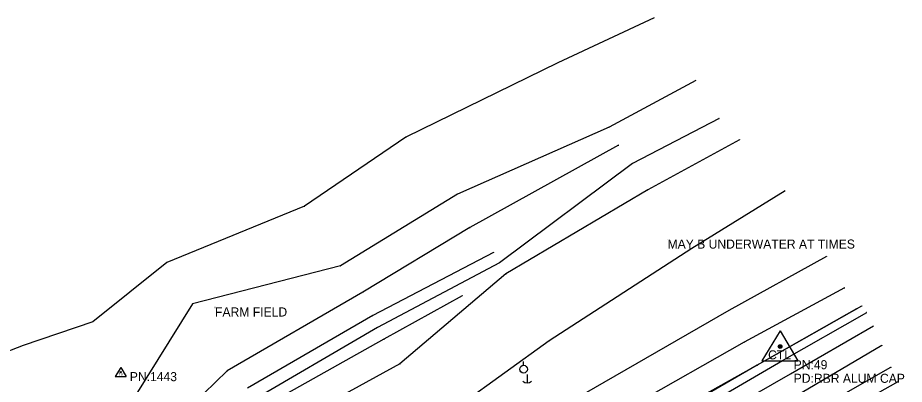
# Model space of a CAD drawing. Extents: x 1419505 to 1434054, y 1956910 to 1968644.
# Drawn here: x 1423305.2 to 1423793.8, y 1959349.3 to 1959551.5 of the extents above; entities that cross this region are included whole.
import ezdxf

# ---------------------------------------------------------------- set-up
doc = ezdxf.new("R2010")
doc.units = 0
for name, color, linetype in [('S_BREAKLINE', 7, 'Continuous'), ('S_DITCHLINE', 7, 'Continuous'), ('S_EDGE_PAVEMENT', 7, 'Continuous'), ('S_GRD_PT_SYM', 7, 'Continuous'), ('S_MSC_PT_SYM', 7, 'Continuous'), ('S_PAVEMENT_CROWN', 7, 'Continuous'), ('S_PRIMARY_CTL', 7, 'Continuous'), ('S_PRIMARY_CTL_ANNOT', 7, 'Continuous'), ('S_RDW_PT_SYM', 7, 'Continuous'), ('S_SECONDARY_CTL', 7, 'Continuous'), ('S_SECONDARY_CTL_ANNOT', 7, 'Continuous'), ('S_SHOULDER', 7, 'Continuous'), ('S_SURVEY_TEXT_ANNOT', 7, 'Continuous'), ('S_UTILITY_POLE', 7, 'Continuous')]:
    doc.layers.add(name, color=color, linetype=linetype)

msp = doc.modelspace()

# ---------------------------------------------------------------- linework, layer by layer
at = {"layer": 'S_BREAKLINE'}
for p, q in [((1423655.9493, 1959551.4129), (1423602.8278, 1959526.6033)), ((1423602.8278, 1959526.6033), (1423519.0004, 1959485.5276)), ((1423678.9158, 1959516.8316), (1423631.0697, 1959491.18)), ((1423631.0697, 1959491.18), (1423547.5183, 1959454.1426)), ((1423519.0004, 1959485.5276), (1423463.2938, 1959447.6392)), ((1423702.9793, 1959484.1715), (1423652.393, 1959456.5407)), ((1423636.372, 1959481.2103), (1423554.3977, 1959435.7824)), ((1423547.5183, 1959454.1426), (1423483.1441, 1959414.669)), ((1423652.393, 1959456.5407), (1423574.271, 1959410.1767)), ((1423728.1139, 1959455.9897), (1423676.7066, 1959424.1897)), ((1423463.2938, 1959447.6392), (1423387.3729, 1959416.4552)), ((1423554.3977, 1959435.7824), (1423495.3649, 1959400.0781)), ((1423676.7066, 1959424.1897), (1423598.1405, 1959373.3034)), ((1423750.9134, 1959419.7534), (1423697.1119, 1959390.0745)), ((1423387.3729, 1959416.4552), (1423346.5723, 1959383.846)), ((1423483.1441, 1959414.669), (1423401.5338, 1959393.6317)), ((1423574.271, 1959410.1767), (1423515.8552, 1959360.5385)), ((1423495.3649, 1959400.0781), (1423420.6961, 1959356.6703)), ((1423760.9351, 1959402.4883), (1423705.6115, 1959372.5493)), ((1423550.0934, 1959398.197), (1423507.0107, 1959374.1404)), ((1423401.5338, 1959393.6317), (1423369.4308, 1959342.0964)), ((1423697.1119, 1959390.0745), (1423617.2978, 1959344.1385)), ((1423767.5305, 1959391.0025), (1423712.7709, 1959359.8295)), ((1423723.3576, 1959365.9369), (1423770.4067, 1959392.5266)), ((1423346.5723, 1959383.846), (1423308.1598, 1959370.7032)), ((1423308.1598, 1959370.7032), (1423285.4454, 1959361.8876)), ((1423507.0107, 1959374.1404), (1423432.3018, 1959332.4447)), ((1423598.1405, 1959373.3034), (1423534.3444, 1959327.3684)), ((1423705.6115, 1959372.5493), (1423625.4253, 1959327.0984)), ((1423677.4347, 1959340.1152), (1423723.3576, 1959365.9369)), ((1423420.6961, 1959356.6703), (1423381.7956, 1959319.3479)), ((1423515.8552, 1959360.5385), (1423445.3007, 1959322.0911)), ((1423712.7709, 1959359.8295), (1423633.4068, 1959314.0375))]:
    msp.add_line(p, q, dxfattribs=at)
at = {"layer": 'S_DITCHLINE'}
for p, q in [((1423691.6846, 1959495.8783), (1423643.9965, 1959471.1427)), ((1423643.9965, 1959471.1427), (1423570.7108, 1959416.3331)), ((1423567.3906, 1959422.0785), (1423500.8393, 1959387.3443)), ((1423570.7108, 1959416.3331), (1423503.4494, 1959380.6948)), ((1423500.8393, 1959387.3443), (1423431.7848, 1959347.1597)), ((1423503.4494, 1959380.6948), (1423430.4317, 1959337.9941))]:
    msp.add_line(p, q, dxfattribs=at)
at = {"layer": 'S_EDGE_PAVEMENT'}
for p, q in [((1423731.1311, 1959355.0572), (1423776.8571, 1959381.5699)), ((1423743.1339, 1959334.1888), (1423786.4687, 1959358.7254)), ((1423684.7071, 1959328.5905), (1423731.1311, 1959355.0572))]:
    msp.add_line(p, q, dxfattribs=at)
at = {"layer": 'S_GRD_PT_SYM'}
for points in [[(1423655.9493, 1959551.4129), (1423655.9493, 1959551.4629), (1423655.9493, 1959551.4129), (1423655.8993, 1959551.4129), (1423655.9493, 1959551.4129), (1423655.9493, 1959551.3629), (1423655.9493, 1959551.4129), (1423655.9993, 1959551.4129)], [(1423602.8278, 1959526.6033), (1423602.8278, 1959526.6533), (1423602.8278, 1959526.6033), (1423602.7778, 1959526.6033), (1423602.8278, 1959526.6033), (1423602.8278, 1959526.5533), (1423602.8278, 1959526.6033), (1423602.8778, 1959526.6033)], [(1423678.9158, 1959516.8316), (1423678.9158, 1959516.8816), (1423678.9158, 1959516.8316), (1423678.8658, 1959516.8316), (1423678.9158, 1959516.8316), (1423678.9158, 1959516.7816), (1423678.9158, 1959516.8316), (1423678.9658, 1959516.8316)], [(1423691.6846, 1959495.8783), (1423691.6846, 1959495.9283), (1423691.6846, 1959495.8783), (1423691.6346, 1959495.8783), (1423691.6846, 1959495.8783), (1423691.6846, 1959495.8283), (1423691.6846, 1959495.8783), (1423691.7346, 1959495.8783)], [(1423631.0697, 1959491.18), (1423631.0697, 1959491.23), (1423631.0697, 1959491.18), (1423631.0197, 1959491.18), (1423631.0697, 1959491.18), (1423631.0697, 1959491.13), (1423631.0697, 1959491.18), (1423631.1197, 1959491.18)], [(1423519.0004, 1959485.5276), (1423519.0004, 1959485.5776), (1423519.0004, 1959485.5276), (1423518.9504, 1959485.5276), (1423519.0004, 1959485.5276), (1423519.0004, 1959485.4776), (1423519.0004, 1959485.5276), (1423519.0504, 1959485.5276)], [(1423702.9793, 1959484.1715), (1423702.9793, 1959484.2215), (1423702.9793, 1959484.1715), (1423702.9293, 1959484.1715), (1423702.9793, 1959484.1715), (1423702.9793, 1959484.1215), (1423702.9793, 1959484.1715), (1423703.0293, 1959484.1715)], [(1423636.372, 1959481.2103), (1423636.372, 1959481.2603), (1423636.372, 1959481.2103), (1423636.322, 1959481.2103), (1423636.372, 1959481.2103), (1423636.372, 1959481.1603), (1423636.372, 1959481.2103), (1423636.422, 1959481.2103)], [(1423643.9965, 1959471.1427), (1423643.9965, 1959471.1927), (1423643.9965, 1959471.1427), (1423643.9465, 1959471.1427), (1423643.9965, 1959471.1427), (1423643.9965, 1959471.0927), (1423643.9965, 1959471.1427), (1423644.0465, 1959471.1427)], [(1423547.5183, 1959454.1426), (1423547.5183, 1959454.1926), (1423547.5183, 1959454.1426), (1423547.4683, 1959454.1426), (1423547.5183, 1959454.1426), (1423547.5183, 1959454.0926), (1423547.5183, 1959454.1426), (1423547.5683, 1959454.1426)], [(1423652.393, 1959456.5407), (1423652.393, 1959456.5907), (1423652.393, 1959456.5407), (1423652.343, 1959456.5407), (1423652.393, 1959456.5407), (1423652.393, 1959456.4907), (1423652.393, 1959456.5407), (1423652.443, 1959456.5407)], [(1423728.1139, 1959455.9897), (1423728.1139, 1959456.0397), (1423728.1139, 1959455.9897), (1423728.0639, 1959455.9897), (1423728.1139, 1959455.9897), (1423728.1139, 1959455.9397), (1423728.1139, 1959455.9897), (1423728.1639, 1959455.9897)], [(1423463.2938, 1959447.6392), (1423463.2938, 1959447.6892), (1423463.2938, 1959447.6392), (1423463.2438, 1959447.6392), (1423463.2938, 1959447.6392), (1423463.2938, 1959447.5892), (1423463.2938, 1959447.6392), (1423463.3438, 1959447.6392)], [(1423554.3977, 1959435.7824), (1423554.3977, 1959435.8324), (1423554.3977, 1959435.7824), (1423554.3477, 1959435.7824), (1423554.3977, 1959435.7824), (1423554.3977, 1959435.7324), (1423554.3977, 1959435.7824), (1423554.4477, 1959435.7824)], [(1423676.7066, 1959424.1897), (1423676.7066, 1959424.2397), (1423676.7066, 1959424.1897), (1423676.6566, 1959424.1897), (1423676.7066, 1959424.1897), (1423676.7066, 1959424.1397), (1423676.7066, 1959424.1897), (1423676.7566, 1959424.1897)], [(1423567.3906, 1959422.0785), (1423567.3906, 1959422.1285), (1423567.3906, 1959422.0785), (1423567.3406, 1959422.0785), (1423567.3906, 1959422.0785), (1423567.3906, 1959422.0285), (1423567.3906, 1959422.0785), (1423567.4406, 1959422.0785)], [(1423750.9134, 1959419.7534), (1423750.9134, 1959419.8034), (1423750.9134, 1959419.7534), (1423750.8634, 1959419.7534), (1423750.9134, 1959419.7534), (1423750.9134, 1959419.7034), (1423750.9134, 1959419.7534), (1423750.9634, 1959419.7534)], [(1423387.3729, 1959416.4552), (1423387.3729, 1959416.5052), (1423387.3729, 1959416.4552), (1423387.3229, 1959416.4552), (1423387.3729, 1959416.4552), (1423387.3729, 1959416.4052), (1423387.3729, 1959416.4552), (1423387.4229, 1959416.4552)], [(1423483.1441, 1959414.669), (1423483.1441, 1959414.719), (1423483.1441, 1959414.669), (1423483.0941, 1959414.669), (1423483.1441, 1959414.669), (1423483.1441, 1959414.619), (1423483.1441, 1959414.669), (1423483.1941, 1959414.669)], [(1423570.7108, 1959416.3331), (1423570.7108, 1959416.3831), (1423570.7108, 1959416.3331), (1423570.6608, 1959416.3331), (1423570.7108, 1959416.3331), (1423570.7108, 1959416.2831), (1423570.7108, 1959416.3331), (1423570.7608, 1959416.3331)], [(1423574.271, 1959410.1767), (1423574.271, 1959410.2267), (1423574.271, 1959410.1767), (1423574.221, 1959410.1767), (1423574.271, 1959410.1767), (1423574.271, 1959410.1267), (1423574.271, 1959410.1767), (1423574.321, 1959410.1767)], [(1423495.3649, 1959400.0781), (1423495.3649, 1959400.1281), (1423495.3649, 1959400.0781), (1423495.3149, 1959400.0781), (1423495.3649, 1959400.0781), (1423495.3649, 1959400.0281), (1423495.3649, 1959400.0781), (1423495.4149, 1959400.0781)], [(1423760.9351, 1959402.4883), (1423760.9351, 1959402.5383), (1423760.9351, 1959402.4883), (1423760.8851, 1959402.4883), (1423760.9351, 1959402.4883), (1423760.9351, 1959402.4383), (1423760.9351, 1959402.4883), (1423760.9851, 1959402.4883)], [(1423550.0934, 1959398.197), (1423550.0934, 1959398.247), (1423550.0934, 1959398.197), (1423550.0434, 1959398.197), (1423550.0934, 1959398.197), (1423550.0934, 1959398.147), (1423550.0934, 1959398.197), (1423550.1434, 1959398.197)], [(1423401.5338, 1959393.6317), (1423401.5338, 1959393.6817), (1423401.5338, 1959393.6317), (1423401.4838, 1959393.6317), (1423401.5338, 1959393.6317), (1423401.5338, 1959393.5817), (1423401.5338, 1959393.6317), (1423401.5838, 1959393.6317)], [(1423697.1119, 1959390.0745), (1423697.1119, 1959390.1245), (1423697.1119, 1959390.0745), (1423697.0619, 1959390.0745), (1423697.1119, 1959390.0745), (1423697.1119, 1959390.0245), (1423697.1119, 1959390.0745), (1423697.1619, 1959390.0745)], [(1423767.5305, 1959391.0025), (1423767.5305, 1959391.0525), (1423767.5305, 1959391.0025), (1423767.4805, 1959391.0025), (1423767.5305, 1959391.0025), (1423767.5305, 1959390.9525), (1423767.5305, 1959391.0025), (1423767.5805, 1959391.0025)], [(1423770.4067, 1959392.5266), (1423770.4067, 1959392.5766), (1423770.4067, 1959392.5266), (1423770.3567, 1959392.5266), (1423770.4067, 1959392.5266), (1423770.4067, 1959392.4766), (1423770.4067, 1959392.5266), (1423770.4567, 1959392.5266)], [(1423500.8393, 1959387.3443), (1423500.8393, 1959387.3943), (1423500.8393, 1959387.3443), (1423500.7893, 1959387.3443), (1423500.8393, 1959387.3443), (1423500.8393, 1959387.2943), (1423500.8393, 1959387.3443), (1423500.8893, 1959387.3443)], [(1423346.5723, 1959383.846), (1423346.5723, 1959383.896), (1423346.5723, 1959383.846), (1423346.5223, 1959383.846), (1423346.5723, 1959383.846), (1423346.5723, 1959383.796), (1423346.5723, 1959383.846), (1423346.6223, 1959383.846)], [(1423503.4494, 1959380.6948), (1423503.4494, 1959380.7448), (1423503.4494, 1959380.6948), (1423503.3994, 1959380.6948), (1423503.4494, 1959380.6948), (1423503.4494, 1959380.6448), (1423503.4494, 1959380.6948), (1423503.4994, 1959380.6948)], [(1423308.1598, 1959370.7032), (1423308.1598, 1959370.7532), (1423308.1598, 1959370.7032), (1423308.1098, 1959370.7032), (1423308.1598, 1959370.7032), (1423308.1598, 1959370.6532), (1423308.1598, 1959370.7032), (1423308.2098, 1959370.7032)], [(1423507.0107, 1959374.1404), (1423507.0107, 1959374.1904), (1423507.0107, 1959374.1404), (1423506.9607, 1959374.1404), (1423507.0107, 1959374.1404), (1423507.0107, 1959374.0904), (1423507.0107, 1959374.1404), (1423507.0607, 1959374.1404)], [(1423598.1405, 1959373.3034), (1423598.1405, 1959373.3534), (1423598.1405, 1959373.3034), (1423598.0905, 1959373.3034), (1423598.1405, 1959373.3034), (1423598.1405, 1959373.2534), (1423598.1405, 1959373.3034), (1423598.1905, 1959373.3034)], [(1423705.6115, 1959372.5493), (1423705.6115, 1959372.5993), (1423705.6115, 1959372.5493), (1423705.5615, 1959372.5493), (1423705.6115, 1959372.5493), (1423705.6115, 1959372.4993), (1423705.6115, 1959372.5493), (1423705.6615, 1959372.5493)], [(1423723.3576, 1959365.9369), (1423723.3576, 1959365.9869), (1423723.3576, 1959365.9369), (1423723.3076, 1959365.9369), (1423723.3576, 1959365.9369), (1423723.3576, 1959365.8869), (1423723.3576, 1959365.9369), (1423723.4076, 1959365.9369)], [(1423420.6961, 1959356.6703), (1423420.6961, 1959356.7203), (1423420.6961, 1959356.6703), (1423420.6461, 1959356.6703), (1423420.6961, 1959356.6703), (1423420.6961, 1959356.6203), (1423420.6961, 1959356.6703), (1423420.7461, 1959356.6703)], [(1423515.8552, 1959360.5385), (1423515.8552, 1959360.5885), (1423515.8552, 1959360.5385), (1423515.8052, 1959360.5385), (1423515.8552, 1959360.5385), (1423515.8552, 1959360.4885), (1423515.8552, 1959360.5385), (1423515.9052, 1959360.5385)], [(1423712.7709, 1959359.8295), (1423712.7709, 1959359.8795), (1423712.7709, 1959359.8295), (1423712.7209, 1959359.8295), (1423712.7709, 1959359.8295), (1423712.7709, 1959359.7795), (1423712.7709, 1959359.8295), (1423712.8209, 1959359.8295)]]:
    msp.add_lwpolyline(points, dxfattribs=at)
at = {"layer": 'S_MSC_PT_SYM'}
for points in [[(1423663.3078, 1959429.157), (1423663.3078, 1959429.207), (1423663.3078, 1959429.157), (1423663.2578, 1959429.157), (1423663.3078, 1959429.157), (1423663.3078, 1959429.107), (1423663.3078, 1959429.157), (1423663.3578, 1959429.157)], [(1423413.9216, 1959391.7046), (1423413.9216, 1959391.7546), (1423413.9216, 1959391.7046), (1423413.8716, 1959391.7046), (1423413.9216, 1959391.7046), (1423413.9216, 1959391.6546), (1423413.9216, 1959391.7046), (1423413.9716, 1959391.7046)]]:
    msp.add_lwpolyline(points, dxfattribs=at)
at = {"layer": 'S_PAVEMENT_CROWN'}
msp.add_line((1423737.4865, 1959345.0415), (1423781.4454, 1959370.8402), dxfattribs=at)
at = {"layer": 'S_PRIMARY_CTL'}
for p, q in [((1423725.3418, 1959378.8356), (1423715.3085, 1959362.3224)), ((1423725.3418, 1959378.8356), (1423735.1661, 1959362.3224)), ((1423715.3085, 1959362.3224), (1423735.1661, 1959362.3224))]:
    msp.add_line(p, q, dxfattribs=at)
for radius in [1.0369, 0.6089, 0.3444]:
    msp.add_circle((1423725.3418, 1959370.1352), radius, dxfattribs=at)
at = {"layer": 'S_RDW_PT_SYM'}
for points in [[(1423773.1068, 1959388.9114), (1423773.1068, 1959388.9614), (1423773.1068, 1959388.9114), (1423773.0568, 1959388.9114), (1423773.1068, 1959388.9114), (1423773.1068, 1959388.8614), (1423773.1068, 1959388.9114), (1423773.1568, 1959388.9114)], [(1423776.8571, 1959381.5699), (1423776.8571, 1959381.6199), (1423776.8571, 1959381.5699), (1423776.8071, 1959381.5699), (1423776.8571, 1959381.5699), (1423776.8571, 1959381.5199), (1423776.8571, 1959381.5699), (1423776.9071, 1959381.5699)], [(1423781.4454, 1959370.8402), (1423781.4454, 1959370.8902), (1423781.4454, 1959370.8402), (1423781.3954, 1959370.8402), (1423781.4454, 1959370.8402), (1423781.4454, 1959370.7902), (1423781.4454, 1959370.8402), (1423781.4954, 1959370.8402)], [(1423726.6528, 1959362.3837), (1423726.6528, 1959362.4337), (1423726.6528, 1959362.3837), (1423726.6028, 1959362.3837), (1423726.6528, 1959362.3837), (1423726.6528, 1959362.3337), (1423726.6528, 1959362.3837), (1423726.7028, 1959362.3837)], [(1423786.4687, 1959358.7254), (1423786.4687, 1959358.7754), (1423786.4687, 1959358.7254), (1423786.4187, 1959358.7254), (1423786.4687, 1959358.7254), (1423786.4687, 1959358.6754), (1423786.4687, 1959358.7254), (1423786.5187, 1959358.7254)], [(1423731.1311, 1959355.0572), (1423731.1311, 1959355.1072), (1423731.1311, 1959355.0572), (1423731.0811, 1959355.0572), (1423731.1311, 1959355.0572), (1423731.1311, 1959355.0072), (1423731.1311, 1959355.0572), (1423731.1811, 1959355.0572)], [(1423790.384, 1959350.8539), (1423790.384, 1959350.9039), (1423790.384, 1959350.8539), (1423790.334, 1959350.8539), (1423790.384, 1959350.8539), (1423790.384, 1959350.8039), (1423790.384, 1959350.8539), (1423790.434, 1959350.8539)]]:
    msp.add_lwpolyline(points, dxfattribs=at)
at = {"layer": 'S_SECONDARY_CTL'}
for p, q in [((1423361.9413, 1959358.6624), (1423358.9313, 1959353.7085)), ((1423361.9413, 1959358.6624), (1423364.8886, 1959353.7085)), ((1423358.9313, 1959353.7085), (1423364.8886, 1959353.7085))]:
    msp.add_line(p, q, dxfattribs=at)
for radius in [0.3111, 0.1827, 0.1033]:
    msp.add_circle((1423361.9413, 1959356.0523), radius, dxfattribs=at)
at = {"layer": 'S_SHOULDER'}
for p, q in [((1423726.6528, 1959362.3837), (1423773.1068, 1959388.9114)), ((1423679.7558, 1959335.1729), (1423726.6528, 1959362.3837)), ((1423748.1872, 1959327.0774), (1423790.384, 1959350.8539))]:
    msp.add_line(p, q, dxfattribs=at)
at = {"layer": 'S_UTILITY_POLE'}
for p, q in [((1423583.8603, 1959359.8056), (1423583.8603, 1959361.9136)), ((1423585.8599, 1959354.7721), (1423585.8599, 1959350.0446))]:
    msp.add_line(p, q, dxfattribs=at)
msp.add_circle((1423583.9826, 1959357.6644), 2.1268, dxfattribs=at)
msp.add_arc((1423585.9226, 1959353.4703), 3.4134, 226.397181, 313.602819, dxfattribs=at)

# ---------------------------------------------------------------- texts
at = {"layer": 'S_PRIMARY_CTL'}
msp.add_text('CTL', height=5, rotation=360, dxfattribs=at).set_placement((1423718.7553, 1959363.0592))
at = {"layer": 'S_PRIMARY_CTL_ANNOT'}
for s, p in [('PN:49', (1423732.8418, 1959357.6352)), ('PD:RBR ALUM CAP', (1423732.8418, 1959350.1352))]:
    msp.add_text(s, height=5, dxfattribs=at).set_placement(p)
at = {"layer": 'S_SECONDARY_CTL'}
msp.add_text('TV', height=1.5, rotation=360, dxfattribs=at).set_placement((1423360.7366, 1959354.041))
at = {"layer": 'S_SECONDARY_CTL_ANNOT'}
msp.add_text('PN:1443', height=5, dxfattribs=at).set_placement((1423366.9413, 1959351.0523))
at = {"layer": 'S_SURVEY_TEXT_ANNOT'}
for s, p in [('MAY B UNDERWATER AT TIMES', (1423663.3078, 1959424.157)), ('FARM FIELD', (1423413.9216, 1959386.7046))]:
    msp.add_text(s, height=5, dxfattribs=at).set_placement(p)

doc.saveas('drawing.dxf')
